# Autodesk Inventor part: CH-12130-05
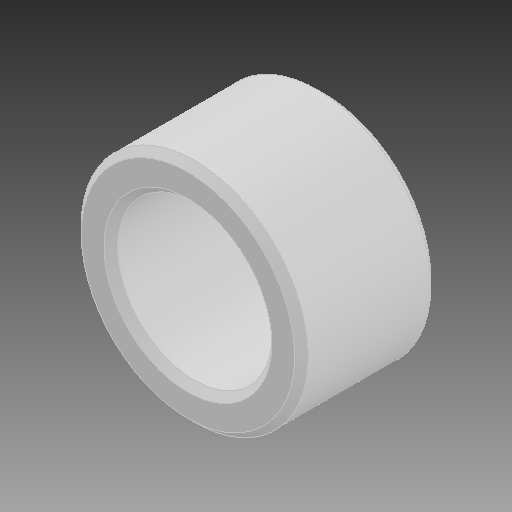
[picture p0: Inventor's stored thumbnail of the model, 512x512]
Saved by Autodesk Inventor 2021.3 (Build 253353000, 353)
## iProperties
Created: 2020-03
Part Number: CH-12130-05
Material: Ogólny
Document SubType Name: Modeling
Designer: Przemyslaw Krecisz
Density: 1 g/cm^3
Appearance: Domyślna
Author: Przemyslaw Krecisz
Revision Number: ÈÎºÎ
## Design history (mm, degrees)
feature "µ¹½Ç1"
node "Bryła1"
